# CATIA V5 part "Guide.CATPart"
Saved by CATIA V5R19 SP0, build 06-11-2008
Part number: Guide
Bounding box of the stored display mesh (mm): x -25 to 25, y -50 to 25, z -10 to 10
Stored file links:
  D:\Shriniwas\v5_r19\c16_CAT_v5r19\c16_Part\Slide curve Joint\Tut_5\Guide.CATPart
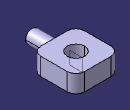
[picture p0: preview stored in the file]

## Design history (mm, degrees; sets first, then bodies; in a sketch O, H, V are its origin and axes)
Body1 (main body)
  Sketch1 on xy-plane, origin (0, 0, 0), H (1, 0, 0), V (0, 1, 0)
    circle A1 centre (0, 0) radius 10
    line L1 (-25, 25) -> (25, 25)
    line L2 (25, 25) -> (25, -25)
    line L3 (25, -25) -> (-25, -25)
    line L4 (-25, -25) -> (-25, 25)
    radius A1 = 10
    length L4 = 50
    length L3 = 50
    distance V L4 = 25
    distance L3 H = 25
    horizontal: L1 H, L3 H
    vertical: L2 V, L4 V
  Pad1: profile Sketch1, direction (0, 0, 1), length 10, mirrored extent
  Sketch2 on face of Pad1 from Sketch1.L3, origin (0, -25, 0), H (1, 0, 0), V (0, 0, 1)
    circle A1 centre (0, 0) radius 7.5
    point P1 (0, 0)
    reference projected line E1 (-25, 10) -> (25, 10) from edge [face of Pad1 from Sketch1.L3 | end face of Pad1]
    radius A1 = 7.5
    distance E1 P1 = 10
    coincidence: P1 V
  Pad2: profile Sketch2, direction (0, -1, 0), length 25
  Fillet1: radius 10, on edge [face of Pad1 from Sketch1.L2 | face of Pad1 from Sketch1.L3]; edge [face of Pad1 from Sketch1.L3 | face of Pad1 from Sketch1.L4]; edge [face of Pad1 from Sketch1.L1 | face of Pad1 from Sketch1.L2]; edge [face of Pad1 from Sketch1.L4 | face of Pad1 from Sketch1.L1]
  Fillet2: radius 2, on edge [face of Pad1 from Sketch1.L3 | face of Pad2 from Sketch2.A1]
